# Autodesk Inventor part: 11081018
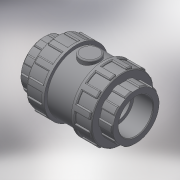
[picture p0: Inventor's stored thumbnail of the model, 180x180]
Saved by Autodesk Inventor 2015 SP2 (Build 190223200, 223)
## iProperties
Created: 2017-11
Part Number: 11081018
Material: Generic
Description: PLASSON CHECK VALVE THR 1 1/4" PTFE COATED SPRING + EPDM O-RING
Document SubType Name: Modeling
Designer: KIM
Density: 1 g/cm^3
Appearance: Default
Author: KIM
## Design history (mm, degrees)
derived "110810 - 110610 110910 - 110010.ipt"
feature "Solid1::110810 - 110610 110910 - 110010.ipt"
tag "TaggingFeature1"
body "Solid1"
other parameters: "d1" = 38.952, "d3" = 26, "d4" = 31.1616, "d5" = 18.2, "d7" = 54.5328, "d8" = 72, "d13" = 1.16856, "d23" = 26, "d24" = 76.8, "d25" = 0.77904, "d26" = 1.16856, "d27" = 12, "d28" = 6, "d29" = 19.5, "d30" = 0, "d35" = 1.16856, "d45" = 360 deg, "d47" = 0.77904, "d51" = 24, "d53" = 0, "d54" = 1.6, "d55" = 7.7904, "d56" = 3.8952, "d58" = 0, "d59" = 1.16856, "d61" = 360 deg, "G_" = 38.952, "l_" = 26
